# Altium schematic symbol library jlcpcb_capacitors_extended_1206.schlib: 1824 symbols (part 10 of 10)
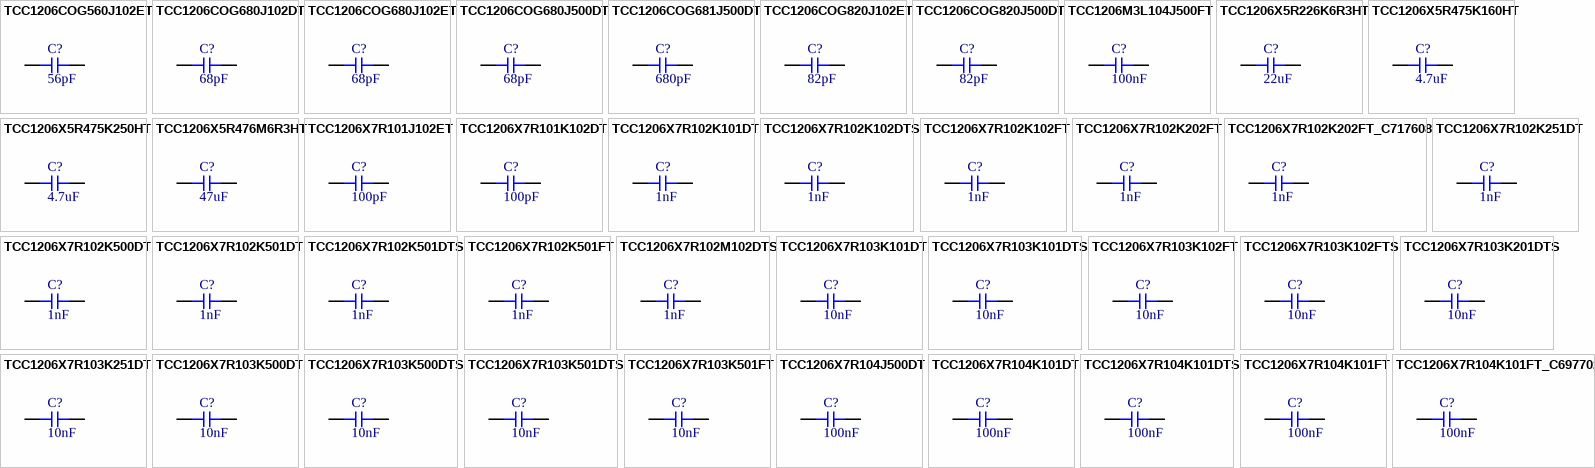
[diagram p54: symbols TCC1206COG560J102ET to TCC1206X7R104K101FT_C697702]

## TCC1206COG680J102DT
designator C?  Capacitance: 68pF  (hidden comment: *)
Capacitor, Ceramic (MLCC), 68pF, ±5%, 1kV, C0G, ±5%, SMD 1206; Manufacturer: CCTC; Manufacturer Part Number: TCC1206COG680J102DT
footprint CAP-1206 (1206 (3216M) Capacitor)
pins: 1, 2

## TCC1206COG680J102ET
designator C?  Capacitance: 68pF  (hidden comment: *)
Capacitor, Ceramic (MLCC), 68pF, ±5%, 1kV, C0G, ±5%, SMD 1206; Manufacturer: CCTC; Manufacturer Part Number: TCC1206COG680J102ET
footprint CAP-1206 (1206 (3216M) Capacitor)
pins: 1, 2

## TCC1206COG680J500DT
designator C?  Capacitance: 68pF  (hidden comment: *)
Capacitor, Ceramic (MLCC), 68pF, ±5%, 50V, C0G, ±5%, SMD 1206; Manufacturer: CCTC; Manufacturer Part Number: TCC1206COG680J500DT
footprint CAP-1206 (1206 (3216M) Capacitor)
pins: 1, 2

## TCC1206COG681J500DT
designator C?  Capacitance: 680pF  (hidden comment: *)
Capacitor, Ceramic (MLCC), 680pF, ±5%, 50V, C0G, ±5%, SMD 1206; Manufacturer: CCTC; Manufacturer Part Number: TCC1206COG681J500DT
footprint CAP-1206 (1206 (3216M) Capacitor)
pins: 1, 2

## TCC1206COG820J102ET
designator C?  Capacitance: 82pF  (hidden comment: *)
Capacitor, Ceramic (MLCC), 82pF, ±5%, 1kV, C0G, ±5%, SMD 1206; Manufacturer: CCTC; Manufacturer Part Number: TCC1206COG820J102ET
footprint CAP-1206 (1206 (3216M) Capacitor)
pins: 1, 2

## TCC1206COG820J500DT
designator C?  Capacitance: 82pF  (hidden comment: *)
Capacitor, Ceramic (MLCC), 82pF, ±5%, 50V, C0G, ±5%, SMD 1206; Manufacturer: CCTC; Manufacturer Part Number: TCC1206COG820J500DT
footprint CAP-1206 (1206 (3216M) Capacitor)
pins: 1, 2

## TCC1206M3L104J500FT
designator C?  Capacitance: 100nF  (hidden comment: *)
Capacitor, Ceramic (MLCC), 100nF, ±5%, 50V, M3L, ±5%, SMD 1206; Manufacturer: CCTC; Manufacturer Part Number: TCC1206M3L104J500FT
footprint CAP-1206 (1206 (3216M) Capacitor)
pins: 1, 2

## TCC1206X5R226K6R3HT
designator C?  Capacitance: 22uF  (hidden comment: *)
Capacitor, Ceramic (MLCC), 22uF, ±10%, 6.3V, X5R, ±10%, SMD 1206; Manufacturer: CCTC; Manufacturer Part Number: TCC1206X5R226K6R3HT
footprint CAP-1206 (1206 (3216M) Capacitor)
pins: 1, 2

## TCC1206X5R475K160HT
designator C?  Capacitance: 4.7uF  (hidden comment: *)
Capacitor, Ceramic (MLCC), 4.7uF, ±10%, 16V, X5R, ±10%, SMD 1206; Manufacturer: CCTC; Manufacturer Part Number: TCC1206X5R475K160HT
footprint CAP-1206 (1206 (3216M) Capacitor)
pins: 1, 2

## TCC1206X5R475K250HT
designator C?  Capacitance: 4.7uF  (hidden comment: *)
Capacitor, Ceramic (MLCC), 4.7uF, ±10%, 25V, X5R, ±10%, SMD 1206; Manufacturer: CCTC; Manufacturer Part Number: TCC1206X5R475K250HT
footprint CAP-1206 (1206 (3216M) Capacitor)
pins: 1, 2

## TCC1206X5R476M6R3HT
designator C?  Capacitance: 47uF  (hidden comment: *)
Capacitor, Ceramic (MLCC), 47uF, ±20%, 6.3V, X5R, ±20%, SMD 1206; Manufacturer: CCTC; Manufacturer Part Number: TCC1206X5R476M6R3HT
footprint CAP-1206 (1206 (3216M) Capacitor)
pins: 1, 2

## TCC1206X7R101J102ET
designator C?  Capacitance: 100pF  (hidden comment: *)
Capacitor, Ceramic (MLCC), 100pF, ±5%, 1kV, X7R, ±5%, SMD 1206; Manufacturer: CCTC; Manufacturer Part Number: TCC1206X7R101J102ET
footprint CAP-1206 (1206 (3216M) Capacitor)
pins: 1, 2

## TCC1206X7R101K102DT
designator C?  Capacitance: 100pF  (hidden comment: *)
Capacitor, Ceramic (MLCC), 100pF, ±10%, 1kV, X7R, ±10%, SMD 1206; Manufacturer: CCTC; Manufacturer Part Number: TCC1206X7R101K102DT
footprint CAP-1206 (1206 (3216M) Capacitor)
pins: 1, 2

## TCC1206X7R102K101DT
designator C?  Capacitance: 1nF  (hidden comment: *)
Capacitor, Ceramic (MLCC), 1nF, ±10%, 100V, X7R, ±10%, SMD 1206; Manufacturer: CCTC; Manufacturer Part Number: TCC1206X7R102K101DT
footprint CAP-1206 (1206 (3216M) Capacitor)
pins: 1, 2

## TCC1206X7R102K102DTS
designator C?  Capacitance: 1nF  (hidden comment: *)
Capacitor, Ceramic (MLCC), 1nF, ±10%, 1kV, X7R, ±10%, SMD 1206; Manufacturer: CCTC; Manufacturer Part Number: TCC1206X7R102K102DTS
footprint CAP-1206 (1206 (3216M) Capacitor)
pins: 1, 2

## TCC1206X7R102K102FT
designator C?  Capacitance: 1nF  (hidden comment: *)
Capacitor, Ceramic (MLCC), 1nF, ±10%, 1kV, X7R, ±10%, SMD 1206; Manufacturer: CCTC; Manufacturer Part Number: TCC1206X7R102K102FT
footprint CAP-1206 (1206 (3216M) Capacitor)
pins: 1, 2

## TCC1206X7R102K202FT
designator C?  Capacitance: 1nF  (hidden comment: *)
Capacitor, Ceramic (MLCC), 1nF, ±10%, 2kV, X7R, ±10%, SMD 1206; Manufacturer: CCTC; Manufacturer Part Number: TCC1206X7R102K202FT
footprint CAP-1206 (1206 (3216M) Capacitor)
pins: 1, 2

## TCC1206X7R102K202FT_C717608
designator C?  Capacitance: 1nF  (hidden comment: *)
Capacitor, Ceramic (MLCC), 1nF, ±10%, 2kV, X7R, ±10%, SMD 1206; Manufacturer: CCTC; Manufacturer Part Number: TCC1206X7R102K202FT
footprint CAP-1206 (1206 (3216M) Capacitor)
pins: 1, 2

## TCC1206X7R102K251DT
designator C?  Capacitance: 1nF  (hidden comment: *)
Capacitor, Ceramic (MLCC), 1nF, ±10%, 250V, X7R, ±10%, SMD 1206; Manufacturer: CCTC; Manufacturer Part Number: TCC1206X7R102K251DT
footprint CAP-1206 (1206 (3216M) Capacitor)
pins: 1, 2

## TCC1206X7R102K500DT
designator C?  Capacitance: 1nF  (hidden comment: *)
Capacitor, Ceramic (MLCC), 1nF, ±10%, 50V, X7R, ±10%, SMD 1206; Manufacturer: CCTC; Manufacturer Part Number: TCC1206X7R102K500DT
footprint CAP-1206 (1206 (3216M) Capacitor)
pins: 1, 2

## TCC1206X7R102K501DT
designator C?  Capacitance: 1nF  (hidden comment: *)
Capacitor, Ceramic (MLCC), 1nF, ±10%, 500V, X7R, ±10%, SMD 1206; Manufacturer: CCTC; Manufacturer Part Number: TCC1206X7R102K501DT
footprint CAP-1206 (1206 (3216M) Capacitor)
pins: 1, 2

## TCC1206X7R102K501DTS
designator C?  Capacitance: 1nF  (hidden comment: *)
Capacitor, Ceramic (MLCC), 1nF, ±10%, 500V, X7R, ±10%, SMD 1206; Manufacturer: CCTC; Manufacturer Part Number: TCC1206X7R102K501DTS
footprint CAP-1206 (1206 (3216M) Capacitor)
pins: 1, 2

## TCC1206X7R102K501FT
designator C?  Capacitance: 1nF  (hidden comment: *)
Capacitor, Ceramic (MLCC), 1nF, ±10%, 500V, X7R, ±10%, SMD 1206; Manufacturer: CCTC; Manufacturer Part Number: TCC1206X7R102K501FT
footprint CAP-1206 (1206 (3216M) Capacitor)
pins: 1, 2

## TCC1206X7R102M102DTS
designator C?  Capacitance: 1nF  (hidden comment: *)
Capacitor, Ceramic (MLCC), 1nF, ±20%, 1kV, X7R, ±20%, SMD 1206; Manufacturer: CCTC; Manufacturer Part Number: TCC1206X7R102M102DTS
footprint CAP-1206 (1206 (3216M) Capacitor)
pins: 1, 2

## TCC1206X7R103K101DT
designator C?  Capacitance: 10nF  (hidden comment: *)
Capacitor, Ceramic (MLCC), 10nF, ±10%, 100V, X7R, ±10%, SMD 1206; Manufacturer: CCTC; Manufacturer Part Number: TCC1206X7R103K101DT
footprint CAP-1206 (1206 (3216M) Capacitor)
pins: 1, 2

## TCC1206X7R103K101DTS
designator C?  Capacitance: 10nF  (hidden comment: *)
Capacitor, Ceramic (MLCC), 10nF, ±10%, 100V, X7R, ±10%, SMD 1206; Manufacturer: CCTC; Manufacturer Part Number: TCC1206X7R103K101DTS
footprint CAP-1206 (1206 (3216M) Capacitor)
pins: 1, 2

## TCC1206X7R103K102FT
designator C?  Capacitance: 10nF  (hidden comment: *)
Capacitor, Ceramic (MLCC), 10nF, ±10%, 1kV, X7R, ±10%, SMD 1206; Manufacturer: CCTC; Manufacturer Part Number: TCC1206X7R103K102FT
footprint CAP-1206 (1206 (3216M) Capacitor)
pins: 1, 2

## TCC1206X7R103K102FTS
designator C?  Capacitance: 10nF  (hidden comment: *)
Capacitor, Ceramic (MLCC), 10nF, ±10%, 1kV, X7R, ±10%, SMD 1206; Manufacturer: CCTC; Manufacturer Part Number: TCC1206X7R103K102FTS
footprint CAP-1206 (1206 (3216M) Capacitor)
pins: 1, 2

## TCC1206X7R103K201DTS
designator C?  Capacitance: 10nF  (hidden comment: *)
Capacitor, Ceramic (MLCC), 10nF, ±10%, 200V, X7R, ±10%, SMD 1206; Manufacturer: CCTC; Manufacturer Part Number: TCC1206X7R103K201DTS
footprint CAP-1206 (1206 (3216M) Capacitor)
pins: 1, 2

## TCC1206X7R103K251DT
designator C?  Capacitance: 10nF  (hidden comment: *)
Capacitor, Ceramic (MLCC), 10nF, ±10%, 250V, X7R, ±10%, SMD 1206; Manufacturer: CCTC; Manufacturer Part Number: TCC1206X7R103K251DT
footprint CAP-1206 (1206 (3216M) Capacitor)
pins: 1, 2

## TCC1206X7R103K500DT
designator C?  Capacitance: 10nF  (hidden comment: *)
Capacitor, Ceramic (MLCC), 10nF, ±10%, 50V, X7R, ±10%, SMD 1206; Manufacturer: CCTC; Manufacturer Part Number: TCC1206X7R103K500DT
footprint CAP-1206 (1206 (3216M) Capacitor)
pins: 1, 2

## TCC1206X7R103K500DTS
designator C?  Capacitance: 10nF  (hidden comment: *)
Capacitor, Ceramic (MLCC), 10nF, ±10%, 50V, X7R, ±10%, SMD 1206; Manufacturer: CCTC; Manufacturer Part Number: TCC1206X7R103K500DTS
footprint CAP-1206 (1206 (3216M) Capacitor)
pins: 1, 2

## TCC1206X7R103K501DTS
designator C?  Capacitance: 10nF  (hidden comment: *)
Capacitor, Ceramic (MLCC), 10nF, ±10%, 500V, X7R, ±10%, SMD 1206; Manufacturer: CCTC; Manufacturer Part Number: TCC1206X7R103K501DTS
footprint CAP-1206 (1206 (3216M) Capacitor)
pins: 1, 2

## TCC1206X7R103K501FT
designator C?  Capacitance: 10nF  (hidden comment: *)
Capacitor, Ceramic (MLCC), 10nF, ±10%, 500V, X7R, ±10%, SMD 1206; Manufacturer: CCTC; Manufacturer Part Number: TCC1206X7R103K501FT
footprint CAP-1206 (1206 (3216M) Capacitor)
pins: 1, 2

## TCC1206X7R104J500DT
designator C?  Capacitance: 100nF  (hidden comment: *)
Capacitor, Ceramic (MLCC), 100nF, ±5%, 50V, X7R, ±5%, SMD 1206; Manufacturer: CCTC; Manufacturer Part Number: TCC1206X7R104J500DT
footprint CAP-1206 (1206 (3216M) Capacitor)
pins: 1, 2

## TCC1206X7R104K101DT
designator C?  Capacitance: 100nF  (hidden comment: *)
Capacitor, Ceramic (MLCC), 100nF, ±10%, 100V, X7R, ±10%, SMD 1206; Manufacturer: CCTC; Manufacturer Part Number: TCC1206X7R104K101DT
footprint CAP-1206 (1206 (3216M) Capacitor)
pins: 1, 2

## TCC1206X7R104K101DTS
designator C?  Capacitance: 100nF  (hidden comment: *)
Capacitor, Ceramic (MLCC), 100nF, ±10%, 100V, X7R, ±10%, SMD 1206; Manufacturer: CCTC; Manufacturer Part Number: TCC1206X7R104K101DTS
footprint CAP-1206 (1206 (3216M) Capacitor)
pins: 1, 2

## TCC1206X7R104K101FT
designator C?  Capacitance: 100nF  (hidden comment: *)
Capacitor, Ceramic (MLCC), 100nF, ±10%, 100V, X7R, ±10%, SMD 1206; Manufacturer: CCTC; Manufacturer Part Number: TCC1206X7R104K101FT
footprint CAP-1206 (1206 (3216M) Capacitor)
pins: 1, 2

## TCC1206X7R104K101FT_C697702
designator C?  Capacitance: 100nF  (hidden comment: *)
Capacitor, Ceramic (MLCC), 100nF, ±10%, 100V, X7R, ±10%, SMD 1206; Manufacturer: CCTC; Manufacturer Part Number: TCC1206X7R104K101FT
footprint CAP-1206 (1206 (3216M) Capacitor)
pins: 1, 2

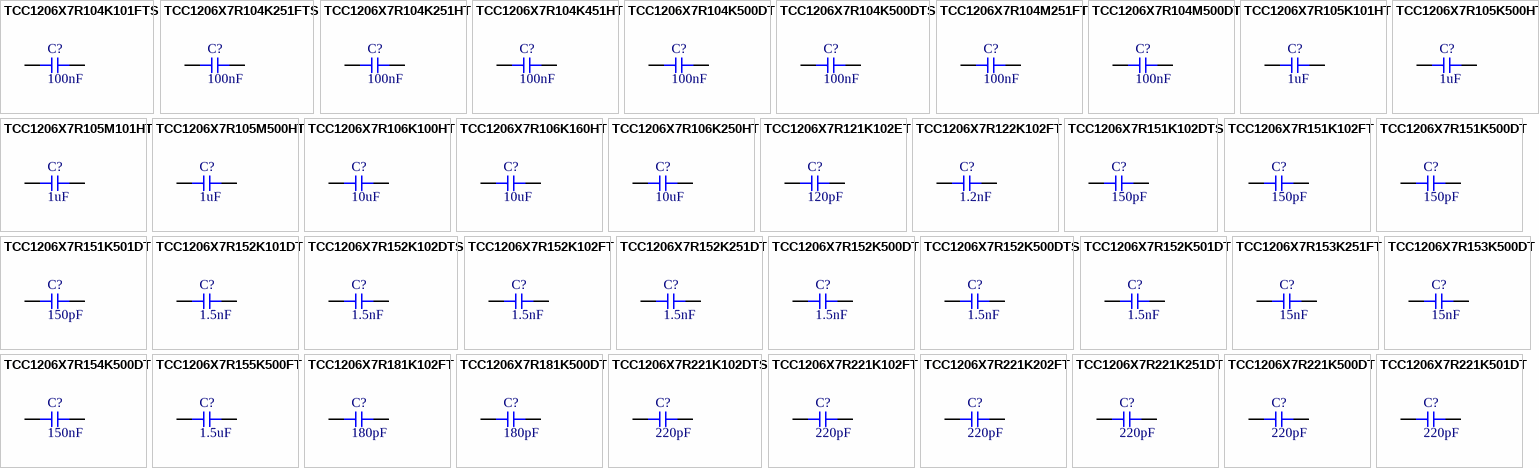
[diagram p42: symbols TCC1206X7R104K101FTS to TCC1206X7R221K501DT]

## TCC1206X7R104K101FTS
designator C?  Capacitance: 100nF  (hidden comment: *)
Capacitor, Ceramic (MLCC), 100nF, ±10%, 100V, X7R, ±10%, SMD 1206; Manufacturer: CCTC; Manufacturer Part Number: TCC1206X7R104K101FTS
footprint CAP-1206 (1206 (3216M) Capacitor)
pins: 1, 2

## TCC1206X7R104K251FTS
designator C?  Capacitance: 100nF  (hidden comment: *)
Capacitor, Ceramic (MLCC), 100nF, ±10%, 250V, X7R, ±10%, SMD 1206; Manufacturer: CCTC; Manufacturer Part Number: TCC1206X7R104K251FTS
footprint CAP-1206 (1206 (3216M) Capacitor)
pins: 1, 2

## TCC1206X7R104K251HT
designator C?  Capacitance: 100nF  (hidden comment: *)
Capacitor, Ceramic (MLCC), 100nF, ±10%, 250V, X7R, ±10%, SMD 1206; Manufacturer: CCTC; Manufacturer Part Number: TCC1206X7R104K251HT
footprint CAP-1206 (1206 (3216M) Capacitor)
pins: 1, 2

## TCC1206X7R104K451HT
designator C?  Capacitance: 100nF  (hidden comment: *)
Capacitor, Ceramic (MLCC), 100nF, ±10%, 450V, X7R, ±10%, SMD 1206; Manufacturer: CCTC; Manufacturer Part Number: TCC1206X7R104K451HT
footprint CAP-1206 (1206 (3216M) Capacitor)
pins: 1, 2

## TCC1206X7R104K500DT
designator C?  Capacitance: 100nF  (hidden comment: *)
Capacitor, Ceramic (MLCC), 100nF, ±10%, 50V, X7R, ±10%, SMD 1206; Manufacturer: CCTC; Manufacturer Part Number: TCC1206X7R104K500DT
footprint CAP-1206 (1206 (3216M) Capacitor)
pins: 1, 2

## TCC1206X7R104K500DTS
designator C?  Capacitance: 100nF  (hidden comment: *)
Capacitor, Ceramic (MLCC), 100nF, ±10%, 50V, X7R, ±10%, SMD 1206; Manufacturer: CCTC; Manufacturer Part Number: TCC1206X7R104K500DTS
footprint CAP-1206 (1206 (3216M) Capacitor)
pins: 1, 2

## TCC1206X7R104M251FT
designator C?  Capacitance: 100nF  (hidden comment: *)
Capacitor, Ceramic (MLCC), 100nF, ±20%, 250V, X7R, ±20%, SMD 1206; Manufacturer: CCTC; Manufacturer Part Number: TCC1206X7R104M251FT
footprint CAP-1206 (1206 (3216M) Capacitor)
pins: 1, 2

## TCC1206X7R104M500DT
designator C?  Capacitance: 100nF  (hidden comment: *)
Capacitor, Ceramic (MLCC), 100nF, ±20%, 50V, X7R, ±20%, SMD 1206; Manufacturer: CCTC; Manufacturer Part Number: TCC1206X7R104M500DT
footprint CAP-1206 (1206 (3216M) Capacitor)
pins: 1, 2

## TCC1206X7R105K101HT
designator C?  Capacitance: 1uF  (hidden comment: *)
Capacitor, Ceramic (MLCC), 1uF, ±10%, 100V, X7R, ±10%, SMD 1206; Manufacturer: CCTC; Manufacturer Part Number: TCC1206X7R105K101HT
footprint CAP-1206 (1206 (3216M) Capacitor)
pins: 1, 2

## TCC1206X7R105K500HT
designator C?  Capacitance: 1uF  (hidden comment: *)
Capacitor, Ceramic (MLCC), 1uF, ±10%, 50V, X7R, ±10%, SMD 1206; Manufacturer: CCTC; Manufacturer Part Number: TCC1206X7R105K500HT
footprint CAP-1206 (1206 (3216M) Capacitor)
pins: 1, 2

## TCC1206X7R105M101HT
designator C?  Capacitance: 1uF  (hidden comment: *)
Capacitor, Ceramic (MLCC), 1uF, ±20%, 100V, X7R, ±20%, SMD 1206; Manufacturer: CCTC; Manufacturer Part Number: TCC1206X7R105M101HT
footprint CAP-1206 (1206 (3216M) Capacitor)
pins: 1, 2

## TCC1206X7R105M500HT
designator C?  Capacitance: 1uF  (hidden comment: *)
Capacitor, Ceramic (MLCC), 1uF, ±20%, 50V, X7R, ±20%, SMD 1206; Manufacturer: CCTC; Manufacturer Part Number: TCC1206X7R105M500HT
footprint CAP-1206 (1206 (3216M) Capacitor)
pins: 1, 2

## TCC1206X7R106K100HT
designator C?  Capacitance: 10uF  (hidden comment: *)
Capacitor, Ceramic (MLCC), 10uF, ±10%, 10V, X7R, ±10%, SMD 1206; Manufacturer: CCTC; Manufacturer Part Number: TCC1206X7R106K100HT
footprint CAP-1206 (1206 (3216M) Capacitor)
pins: 1, 2

## TCC1206X7R106K160HT
designator C?  Capacitance: 10uF  (hidden comment: *)
Capacitor, Ceramic (MLCC), 10uF, ±10%, 16V, X7R, ±10%, SMD 1206; Manufacturer: CCTC; Manufacturer Part Number: TCC1206X7R106K160HT
footprint CAP-1206 (1206 (3216M) Capacitor)
pins: 1, 2

## TCC1206X7R106K250HT
designator C?  Capacitance: 10uF  (hidden comment: *)
Capacitor, Ceramic (MLCC), 10uF, ±10%, 25V, X7R, ±10%, SMD 1206; Manufacturer: CCTC; Manufacturer Part Number: TCC1206X7R106K250HT
footprint CAP-1206 (1206 (3216M) Capacitor)
pins: 1, 2

## TCC1206X7R121K102ET
designator C?  Capacitance: 120pF  (hidden comment: *)
Capacitor, Ceramic (MLCC), 120pF, ±10%, 1kV, X7R, ±10%, SMD 1206; Manufacturer: CCTC; Manufacturer Part Number: TCC1206X7R121K102ET
footprint CAP-1206 (1206 (3216M) Capacitor)
pins: 1, 2

## TCC1206X7R122K102FT
designator C?  Capacitance: 1.2nF  (hidden comment: *)
Capacitor, Ceramic (MLCC), 1.2nF, ±10%, 1kV, X7R, ±10%, SMD 1206; Manufacturer: CCTC; Manufacturer Part Number: TCC1206X7R122K102FT
footprint CAP-1206 (1206 (3216M) Capacitor)
pins: 1, 2

## TCC1206X7R151K102DTS
designator C?  Capacitance: 150pF  (hidden comment: *)
Capacitor, Ceramic (MLCC), 150pF, ±10%, 1kV, X7R, ±10%, SMD 1206; Manufacturer: CCTC; Manufacturer Part Number: TCC1206X7R151K102DTS
footprint CAP-1206 (1206 (3216M) Capacitor)
pins: 1, 2

## TCC1206X7R151K102FT
designator C?  Capacitance: 150pF  (hidden comment: *)
Capacitor, Ceramic (MLCC), 150pF, ±10%, 1kV, X7R, ±10%, SMD 1206; Manufacturer: CCTC; Manufacturer Part Number: TCC1206X7R151K102FT
footprint CAP-1206 (1206 (3216M) Capacitor)
pins: 1, 2

## TCC1206X7R151K500DT
designator C?  Capacitance: 150pF  (hidden comment: *)
Capacitor, Ceramic (MLCC), 150pF, ±10%, 50V, X7R, ±10%, SMD 1206; Manufacturer: CCTC; Manufacturer Part Number: TCC1206X7R151K500DT
footprint CAP-1206 (1206 (3216M) Capacitor)
pins: 1, 2

## TCC1206X7R151K501DT
designator C?  Capacitance: 150pF  (hidden comment: *)
Capacitor, Ceramic (MLCC), 150pF, ±10%, 500V, X7R, ±10%, SMD 1206; Manufacturer: CCTC; Manufacturer Part Number: TCC1206X7R151K501DT
footprint CAP-1206 (1206 (3216M) Capacitor)
pins: 1, 2

## TCC1206X7R152K101DT
designator C?  Capacitance: 1.5nF  (hidden comment: *)
Capacitor, Ceramic (MLCC), 1.5nF, ±10%, 100V, X7R, ±10%, SMD 1206; Manufacturer: CCTC; Manufacturer Part Number: TCC1206X7R152K101DT
footprint CAP-1206 (1206 (3216M) Capacitor)
pins: 1, 2

## TCC1206X7R152K102DTS
designator C?  Capacitance: 1.5nF  (hidden comment: *)
Capacitor, Ceramic (MLCC), 1.5nF, ±10%, 1kV, X7R, ±10%, SMD 1206; Manufacturer: CCTC; Manufacturer Part Number: TCC1206X7R152K102DTS
footprint CAP-1206 (1206 (3216M) Capacitor)
pins: 1, 2

## TCC1206X7R152K102FT
designator C?  Capacitance: 1.5nF  (hidden comment: *)
Capacitor, Ceramic (MLCC), 1.5nF, ±10%, 1kV, X7R, ±10%, SMD 1206; Manufacturer: CCTC; Manufacturer Part Number: TCC1206X7R152K102FT
footprint CAP-1206 (1206 (3216M) Capacitor)
pins: 1, 2

## TCC1206X7R152K251DT
designator C?  Capacitance: 1.5nF  (hidden comment: *)
Capacitor, Ceramic (MLCC), 1.5nF, ±10%, 250V, X7R, ±10%, SMD 1206; Manufacturer: CCTC; Manufacturer Part Number: TCC1206X7R152K251DT
footprint CAP-1206 (1206 (3216M) Capacitor)
pins: 1, 2

## TCC1206X7R152K500DT
designator C?  Capacitance: 1.5nF  (hidden comment: *)
Capacitor, Ceramic (MLCC), 1.5nF, ±10%, 50V, X7R, ±10%, SMD 1206; Manufacturer: CCTC; Manufacturer Part Number: TCC1206X7R152K500DT
footprint CAP-1206 (1206 (3216M) Capacitor)
pins: 1, 2

## TCC1206X7R152K500DTS
designator C?  Capacitance: 1.5nF  (hidden comment: *)
Capacitor, Ceramic (MLCC), 1.5nF, ±10%, 50V, X7R, ±10%, SMD 1206; Manufacturer: CCTC; Manufacturer Part Number: TCC1206X7R152K500DTS
footprint CAP-1206 (1206 (3216M) Capacitor)
pins: 1, 2

## TCC1206X7R152K501DT
designator C?  Capacitance: 1.5nF  (hidden comment: *)
Capacitor, Ceramic (MLCC), 1.5nF, ±10%, 500V, X7R, ±10%, SMD 1206; Manufacturer: CCTC; Manufacturer Part Number: TCC1206X7R152K501DT
footprint CAP-1206 (1206 (3216M) Capacitor)
pins: 1, 2

## TCC1206X7R153K251FT
designator C?  Capacitance: 15nF  (hidden comment: *)
Capacitor, Ceramic (MLCC), 15nF, ±10%, 250V, X7R, ±10%, SMD 1206; Manufacturer: CCTC; Manufacturer Part Number: TCC1206X7R153K251FT
footprint CAP-1206 (1206 (3216M) Capacitor)
pins: 1, 2

## TCC1206X7R153K500DT
designator C?  Capacitance: 15nF  (hidden comment: *)
Capacitor, Ceramic (MLCC), 15nF, ±10%, 50V, X7R, ±10%, SMD 1206; Manufacturer: CCTC; Manufacturer Part Number: TCC1206X7R153K500DT
footprint CAP-1206 (1206 (3216M) Capacitor)
pins: 1, 2

## TCC1206X7R154K500DT
designator C?  Capacitance: 150nF  (hidden comment: *)
Capacitor, Ceramic (MLCC), 150nF, ±10%, 50V, X7R, ±10%, SMD 1206; Manufacturer: CCTC; Manufacturer Part Number: TCC1206X7R154K500DT
footprint CAP-1206 (1206 (3216M) Capacitor)
pins: 1, 2

## TCC1206X7R155K500FT
designator C?  Capacitance: 1.5uF  (hidden comment: *)
Capacitor, Ceramic (MLCC), 1.5uF, ±10%, 50V, X7R, ±10%, SMD 1206; Manufacturer: CCTC; Manufacturer Part Number: TCC1206X7R155K500FT
footprint CAP-1206 (1206 (3216M) Capacitor)
pins: 1, 2

## TCC1206X7R181K102FT
designator C?  Capacitance: 180pF  (hidden comment: *)
Capacitor, Ceramic (MLCC), 180pF, ±10%, 1kV, X7R, ±10%, SMD 1206; Manufacturer: CCTC; Manufacturer Part Number: TCC1206X7R181K102FT
footprint CAP-1206 (1206 (3216M) Capacitor)
pins: 1, 2

## TCC1206X7R181K500DT
designator C?  Capacitance: 180pF  (hidden comment: *)
Capacitor, Ceramic (MLCC), 180pF, ±10%, 50V, X7R, ±10%, SMD 1206; Manufacturer: CCTC; Manufacturer Part Number: TCC1206X7R181K500DT
footprint CAP-1206 (1206 (3216M) Capacitor)
pins: 1, 2

## TCC1206X7R221K102DTS
designator C?  Capacitance: 220pF  (hidden comment: *)
Capacitor, Ceramic (MLCC), 220pF, ±10%, 1kV, X7R, ±10%, SMD 1206; Manufacturer: CCTC; Manufacturer Part Number: TCC1206X7R221K102DTS
footprint CAP-1206 (1206 (3216M) Capacitor)
pins: 1, 2

## TCC1206X7R221K102FT
designator C?  Capacitance: 220pF  (hidden comment: *)
Capacitor, Ceramic (MLCC), 220pF, ±10%, 1kV, X7R, ±10%, SMD 1206; Manufacturer: CCTC; Manufacturer Part Number: TCC1206X7R221K102FT
footprint CAP-1206 (1206 (3216M) Capacitor)
pins: 1, 2

## TCC1206X7R221K202FT
designator C?  Capacitance: 220pF  (hidden comment: *)
Capacitor, Ceramic (MLCC), 220pF, ±10%, 2kV, X7R, ±10%, SMD 1206; Manufacturer: CCTC; Manufacturer Part Number: TCC1206X7R221K202FT
footprint CAP-1206 (1206 (3216M) Capacitor)
pins: 1, 2

## TCC1206X7R221K251DT
designator C?  Capacitance: 220pF  (hidden comment: *)
Capacitor, Ceramic (MLCC), 220pF, ±10%, 250V, X7R, ±10%, SMD 1206; Manufacturer: CCTC; Manufacturer Part Number: TCC1206X7R221K251DT
footprint CAP-1206 (1206 (3216M) Capacitor)
pins: 1, 2

## TCC1206X7R221K500DT
designator C?  Capacitance: 220pF  (hidden comment: *)
Capacitor, Ceramic (MLCC), 220pF, ±10%, 50V, X7R, ±10%, SMD 1206; Manufacturer: CCTC; Manufacturer Part Number: TCC1206X7R221K500DT
footprint CAP-1206 (1206 (3216M) Capacitor)
pins: 1, 2

## TCC1206X7R221K501DT
designator C?  Capacitance: 220pF  (hidden comment: *)
Capacitor, Ceramic (MLCC), 220pF, ±10%, 500V, X7R, ±10%, SMD 1206; Manufacturer: CCTC; Manufacturer Part Number: TCC1206X7R221K501DT
footprint CAP-1206 (1206 (3216M) Capacitor)
pins: 1, 2

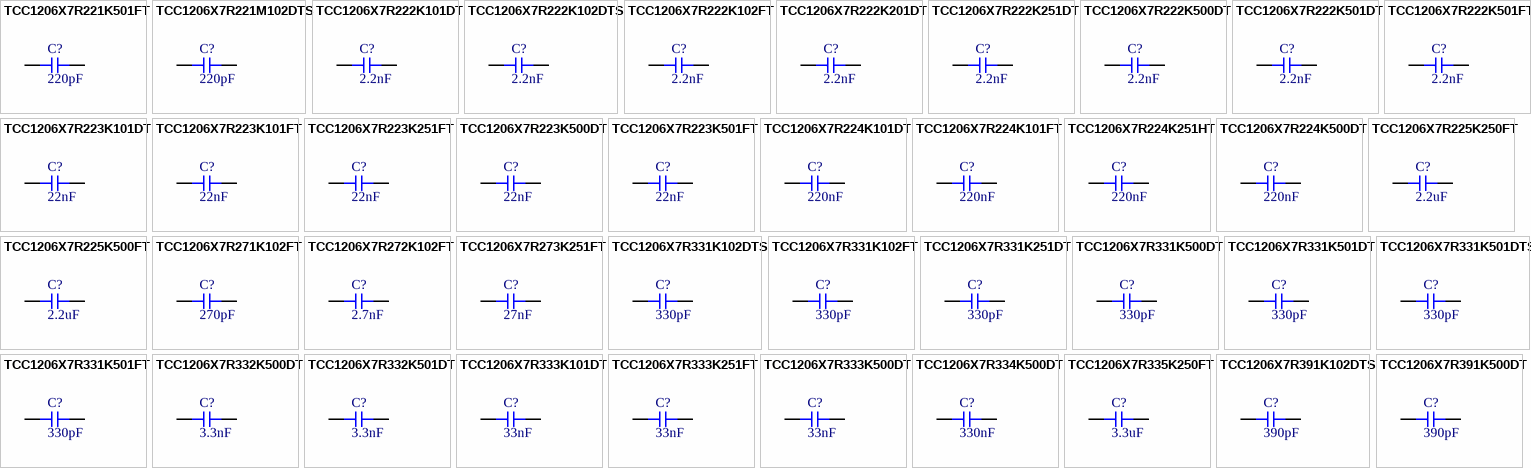
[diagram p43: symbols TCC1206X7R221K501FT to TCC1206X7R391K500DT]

## TCC1206X7R221K501FT
designator C?  Capacitance: 220pF  (hidden comment: *)
Capacitor, Ceramic (MLCC), 220pF, ±10%, 500V, X7R, ±10%, SMD 1206; Manufacturer: CCTC; Manufacturer Part Number: TCC1206X7R221K501FT
footprint CAP-1206 (1206 (3216M) Capacitor)
pins: 1, 2

## TCC1206X7R221M102DTS
designator C?  Capacitance: 220pF  (hidden comment: *)
Capacitor, Ceramic (MLCC), 220pF, ±20%, 1kV, X7R, ±20%, SMD 1206; Manufacturer: CCTC; Manufacturer Part Number: TCC1206X7R221M102DTS
footprint CAP-1206 (1206 (3216M) Capacitor)
pins: 1, 2

## TCC1206X7R222K101DT
designator C?  Capacitance: 2.2nF  (hidden comment: *)
Capacitor, Ceramic (MLCC), 2.2nF, ±10%, 100V, X7R, ±10%, SMD 1206; Manufacturer: CCTC; Manufacturer Part Number: TCC1206X7R222K101DT
footprint CAP-1206 (1206 (3216M) Capacitor)
pins: 1, 2

## TCC1206X7R222K102DTS
designator C?  Capacitance: 2.2nF  (hidden comment: *)
Capacitor, Ceramic (MLCC), 2.2nF, ±10%, 1kV, X7R, ±10%, SMD 1206; Manufacturer: CCTC; Manufacturer Part Number: TCC1206X7R222K102DTS
footprint CAP-1206 (1206 (3216M) Capacitor)
pins: 1, 2

## TCC1206X7R222K102FT
designator C?  Capacitance: 2.2nF  (hidden comment: *)
Capacitor, Ceramic (MLCC), 2.2nF, ±10%, 1kV, X7R, ±10%, SMD 1206; Manufacturer: CCTC; Manufacturer Part Number: TCC1206X7R222K102FT
footprint CAP-1206 (1206 (3216M) Capacitor)
pins: 1, 2

## TCC1206X7R222K201DT
designator C?  Capacitance: 2.2nF  (hidden comment: *)
Capacitor, Ceramic (MLCC), 2.2nF, ±10%, 200V, X7R, ±10%, SMD 1206; Manufacturer: CCTC; Manufacturer Part Number: TCC1206X7R222K201DT
footprint CAP-1206 (1206 (3216M) Capacitor)
pins: 1, 2

## TCC1206X7R222K251DT
designator C?  Capacitance: 2.2nF  (hidden comment: *)
Capacitor, Ceramic (MLCC), 2.2nF, ±10%, 250V, X7R, ±10%, SMD 1206; Manufacturer: CCTC; Manufacturer Part Number: TCC1206X7R222K251DT
footprint CAP-1206 (1206 (3216M) Capacitor)
pins: 1, 2

## TCC1206X7R222K500DT
designator C?  Capacitance: 2.2nF  (hidden comment: *)
Capacitor, Ceramic (MLCC), 2.2nF, ±10%, 50V, X7R, ±10%, SMD 1206; Manufacturer: CCTC; Manufacturer Part Number: TCC1206X7R222K500DT
footprint CAP-1206 (1206 (3216M) Capacitor)
pins: 1, 2

## TCC1206X7R222K501DT
designator C?  Capacitance: 2.2nF  (hidden comment: *)
Capacitor, Ceramic (MLCC), 2.2nF, ±10%, 500V, X7R, ±10%, SMD 1206; Manufacturer: CCTC; Manufacturer Part Number: TCC1206X7R222K501DT
footprint CAP-1206 (1206 (3216M) Capacitor)
pins: 1, 2

## TCC1206X7R222K501FT
designator C?  Capacitance: 2.2nF  (hidden comment: *)
Capacitor, Ceramic (MLCC), 2.2nF, ±10%, 500V, X7R, ±10%, SMD 1206; Manufacturer: CCTC; Manufacturer Part Number: TCC1206X7R222K501FT
footprint CAP-1206 (1206 (3216M) Capacitor)
pins: 1, 2

## TCC1206X7R223K101DT
designator C?  Capacitance: 22nF  (hidden comment: *)
Capacitor, Ceramic (MLCC), 22nF, ±10%, 100V, X7R, ±10%, SMD 1206; Manufacturer: CCTC; Manufacturer Part Number: TCC1206X7R223K101DT
footprint CAP-1206 (1206 (3216M) Capacitor)
pins: 1, 2

## TCC1206X7R223K101FT
designator C?  Capacitance: 22nF  (hidden comment: *)
Capacitor, Ceramic (MLCC), 22nF, ±10%, 100V, X7R, ±10%, SMD 1206; Manufacturer: CCTC; Manufacturer Part Number: TCC1206X7R223K101FT
footprint CAP-1206 (1206 (3216M) Capacitor)
pins: 1, 2

## TCC1206X7R223K251FT
designator C?  Capacitance: 22nF  (hidden comment: *)
Capacitor, Ceramic (MLCC), 22nF, ±10%, 250V, X7R, ±10%, SMD 1206; Manufacturer: CCTC; Manufacturer Part Number: TCC1206X7R223K251FT
footprint CAP-1206 (1206 (3216M) Capacitor)
pins: 1, 2

## TCC1206X7R223K500DT
designator C?  Capacitance: 22nF  (hidden comment: *)
Capacitor, Ceramic (MLCC), 22nF, ±10%, 50V, X7R, ±10%, SMD 1206; Manufacturer: CCTC; Manufacturer Part Number: TCC1206X7R223K500DT
footprint CAP-1206 (1206 (3216M) Capacitor)
pins: 1, 2

## TCC1206X7R223K501FT
designator C?  Capacitance: 22nF  (hidden comment: *)
Capacitor, Ceramic (MLCC), 22nF, ±10%, 500V, X7R, ±10%, SMD 1206; Manufacturer: CCTC; Manufacturer Part Number: TCC1206X7R223K501FT
footprint CAP-1206 (1206 (3216M) Capacitor)
pins: 1, 2

## TCC1206X7R224K101DT
designator C?  Capacitance: 220nF  (hidden comment: *)
Capacitor, Ceramic (MLCC), 220nF, ±10%, 100V, X7R, ±10%, SMD 1206; Manufacturer: CCTC; Manufacturer Part Number: TCC1206X7R224K101DT
footprint CAP-1206 (1206 (3216M) Capacitor)
pins: 1, 2

## TCC1206X7R224K101FT
designator C?  Capacitance: 220nF  (hidden comment: *)
Capacitor, Ceramic (MLCC), 220nF, ±10%, 100V, X7R, ±10%, SMD 1206; Manufacturer: CCTC; Manufacturer Part Number: TCC1206X7R224K101FT
footprint CAP-1206 (1206 (3216M) Capacitor)
pins: 1, 2

## TCC1206X7R224K251HT
designator C?  Capacitance: 220nF  (hidden comment: *)
Capacitor, Ceramic (MLCC), 220nF, ±10%, 250V, X7R, ±10%, SMD 1206; Manufacturer: CCTC; Manufacturer Part Number: TCC1206X7R224K251HT
footprint CAP-1206 (1206 (3216M) Capacitor)
pins: 1, 2

## TCC1206X7R224K500DT
designator C?  Capacitance: 220nF  (hidden comment: *)
Capacitor, Ceramic (MLCC), 220nF, ±10%, 50V, X7R, ±10%, SMD 1206; Manufacturer: CCTC; Manufacturer Part Number: TCC1206X7R224K500DT
footprint CAP-1206 (1206 (3216M) Capacitor)
pins: 1, 2

## TCC1206X7R225K250FT
designator C?  Capacitance: 2.2uF  (hidden comment: *)
Capacitor, Ceramic (MLCC), 2.2uF, ±10%, 25V, X7R, ±10%, SMD 1206; Manufacturer: CCTC; Manufacturer Part Number: TCC1206X7R225K250FT
footprint CAP-1206 (1206 (3216M) Capacitor)
pins: 1, 2

## TCC1206X7R225K500FT
designator C?  Capacitance: 2.2uF  (hidden comment: *)
Capacitor, Ceramic (MLCC), 2.2uF, ±10%, 50V, X7R, ±10%, SMD 1206; Manufacturer: CCTC; Manufacturer Part Number: TCC1206X7R225K500FT
footprint CAP-1206 (1206 (3216M) Capacitor)
pins: 1, 2

## TCC1206X7R271K102FT
designator C?  Capacitance: 270pF  (hidden comment: *)
Capacitor, Ceramic (MLCC), 270pF, ±10%, 1kV, X7R, ±10%, SMD 1206; Manufacturer: CCTC; Manufacturer Part Number: TCC1206X7R271K102FT
footprint CAP-1206 (1206 (3216M) Capacitor)
pins: 1, 2

## TCC1206X7R272K102FT
designator C?  Capacitance: 2.7nF  (hidden comment: *)
Capacitor, Ceramic (MLCC), 2.7nF, ±10%, 1kV, X7R, ±10%, SMD 1206; Manufacturer: CCTC; Manufacturer Part Number: TCC1206X7R272K102FT
footprint CAP-1206 (1206 (3216M) Capacitor)
pins: 1, 2

## TCC1206X7R273K251FT
designator C?  Capacitance: 27nF  (hidden comment: *)
Capacitor, Ceramic (MLCC), 27nF, ±10%, 250V, X7R, ±10%, SMD 1206; Manufacturer: CCTC; Manufacturer Part Number: TCC1206X7R273K251FT
footprint CAP-1206 (1206 (3216M) Capacitor)
pins: 1, 2

## TCC1206X7R331K102DTS
designator C?  Capacitance: 330pF  (hidden comment: *)
Capacitor, Ceramic (MLCC), 330pF, ±10%, 1kV, X7R, ±10%, SMD 1206; Manufacturer: CCTC; Manufacturer Part Number: TCC1206X7R331K102DTS
footprint CAP-1206 (1206 (3216M) Capacitor)
pins: 1, 2

## TCC1206X7R331K102FT
designator C?  Capacitance: 330pF  (hidden comment: *)
Capacitor, Ceramic (MLCC), 330pF, ±10%, 1kV, X7R, ±10%, SMD 1206; Manufacturer: CCTC; Manufacturer Part Number: TCC1206X7R331K102FT
footprint CAP-1206 (1206 (3216M) Capacitor)
pins: 1, 2

## TCC1206X7R331K251DT
designator C?  Capacitance: 330pF  (hidden comment: *)
Capacitor, Ceramic (MLCC), 330pF, ±10%, 250V, X7R, ±10%, SMD 1206; Manufacturer: CCTC; Manufacturer Part Number: TCC1206X7R331K251DT
footprint CAP-1206 (1206 (3216M) Capacitor)
pins: 1, 2

## TCC1206X7R331K500DT
designator C?  Capacitance: 330pF  (hidden comment: *)
Capacitor, Ceramic (MLCC), 330pF, ±10%, 50V, X7R, ±10%, SMD 1206; Manufacturer: CCTC; Manufacturer Part Number: TCC1206X7R331K500DT
footprint CAP-1206 (1206 (3216M) Capacitor)
pins: 1, 2

## TCC1206X7R331K501DT
designator C?  Capacitance: 330pF  (hidden comment: *)
Capacitor, Ceramic (MLCC), 330pF, ±10%, 500V, X7R, ±10%, SMD 1206; Manufacturer: CCTC; Manufacturer Part Number: TCC1206X7R331K501DT
footprint CAP-1206 (1206 (3216M) Capacitor)
pins: 1, 2

## TCC1206X7R331K501DTS
designator C?  Capacitance: 330pF  (hidden comment: *)
Capacitor, Ceramic (MLCC), 330pF, ±10%, 500V, X7R, ±10%, SMD 1206; Manufacturer: CCTC; Manufacturer Part Number: TCC1206X7R331K501DTS
footprint CAP-1206 (1206 (3216M) Capacitor)
pins: 1, 2

## TCC1206X7R331K501FT
designator C?  Capacitance: 330pF  (hidden comment: *)
Capacitor, Ceramic (MLCC), 330pF, ±10%, 500V, X7R, ±10%, SMD 1206; Manufacturer: CCTC; Manufacturer Part Number: TCC1206X7R331K501FT
footprint CAP-1206 (1206 (3216M) Capacitor)
pins: 1, 2

## TCC1206X7R332K500DT
designator C?  Capacitance: 3.3nF  (hidden comment: *)
Capacitor, Ceramic (MLCC), 3.3nF, ±10%, 50V, X7R, ±10%, SMD 1206; Manufacturer: CCTC; Manufacturer Part Number: TCC1206X7R332K500DT
footprint CAP-1206 (1206 (3216M) Capacitor)
pins: 1, 2

## TCC1206X7R332K501DT
designator C?  Capacitance: 3.3nF  (hidden comment: *)
Capacitor, Ceramic (MLCC), 3.3nF, ±10%, 500V, X7R, ±10%, SMD 1206; Manufacturer: CCTC; Manufacturer Part Number: TCC1206X7R332K501DT
footprint CAP-1206 (1206 (3216M) Capacitor)
pins: 1, 2

## TCC1206X7R333K101DT
designator C?  Capacitance: 33nF  (hidden comment: *)
Capacitor, Ceramic (MLCC), 33nF, ±10%, 100V, X7R, ±10%, SMD 1206; Manufacturer: CCTC; Manufacturer Part Number: TCC1206X7R333K101DT
footprint CAP-1206 (1206 (3216M) Capacitor)
pins: 1, 2

## TCC1206X7R333K251FT
designator C?  Capacitance: 33nF  (hidden comment: *)
Capacitor, Ceramic (MLCC), 33nF, ±10%, 250V, X7R, ±10%, SMD 1206; Manufacturer: CCTC; Manufacturer Part Number: TCC1206X7R333K251FT
footprint CAP-1206 (1206 (3216M) Capacitor)
pins: 1, 2

## TCC1206X7R333K500DT
designator C?  Capacitance: 33nF  (hidden comment: *)
Capacitor, Ceramic (MLCC), 33nF, ±10%, 50V, X7R, ±10%, SMD 1206; Manufacturer: CCTC; Manufacturer Part Number: TCC1206X7R333K500DT
footprint CAP-1206 (1206 (3216M) Capacitor)
pins: 1, 2

## TCC1206X7R334K500DT
designator C?  Capacitance: 330nF  (hidden comment: *)
Capacitor, Ceramic (MLCC), 330nF, ±10%, 50V, X7R, ±10%, SMD 1206; Manufacturer: CCTC; Manufacturer Part Number: TCC1206X7R334K500DT
footprint CAP-1206 (1206 (3216M) Capacitor)
pins: 1, 2

## TCC1206X7R335K250FT
designator C?  Capacitance: 3.3uF  (hidden comment: *)
Capacitor, Ceramic (MLCC), 3.3uF, ±10%, 25V, X7R, ±10%, SMD 1206; Manufacturer: CCTC; Manufacturer Part Number: TCC1206X7R335K250FT
footprint CAP-1206 (1206 (3216M) Capacitor)
pins: 1, 2

## TCC1206X7R391K102DTS
designator C?  Capacitance: 390pF  (hidden comment: *)
Capacitor, Ceramic (MLCC), 390pF, ±10%, 1kV, X7R, ±10%, SMD 1206; Manufacturer: CCTC; Manufacturer Part Number: TCC1206X7R391K102DTS
footprint CAP-1206 (1206 (3216M) Capacitor)
pins: 1, 2

## TCC1206X7R391K500DT
designator C?  Capacitance: 390pF  (hidden comment: *)
Capacitor, Ceramic (MLCC), 390pF, ±10%, 50V, X7R, ±10%, SMD 1206; Manufacturer: CCTC; Manufacturer Part Number: TCC1206X7R391K500DT
footprint CAP-1206 (1206 (3216M) Capacitor)
pins: 1, 2

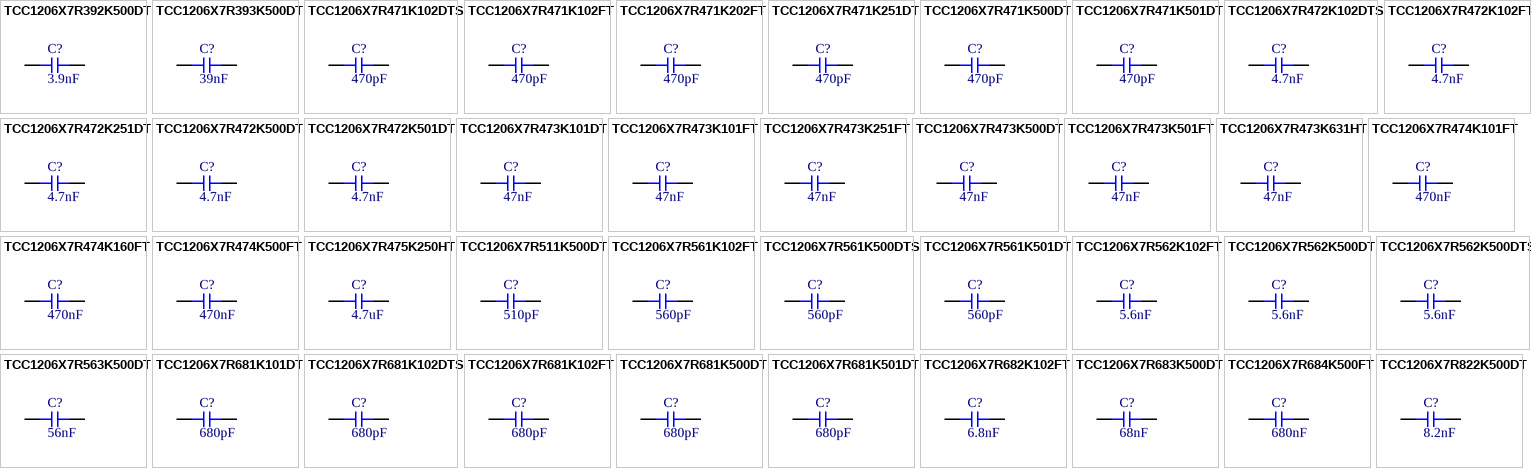
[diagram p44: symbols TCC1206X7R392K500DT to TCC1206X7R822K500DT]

## TCC1206X7R392K500DT
designator C?  Capacitance: 3.9nF  (hidden comment: *)
Capacitor, Ceramic (MLCC), 3.9nF, ±10%, 50V, X7R, ±10%, SMD 1206; Manufacturer: CCTC; Manufacturer Part Number: TCC1206X7R392K500DT
footprint CAP-1206 (1206 (3216M) Capacitor)
pins: 1, 2

## TCC1206X7R393K500DT
designator C?  Capacitance: 39nF  (hidden comment: *)
Capacitor, Ceramic (MLCC), 39nF, ±10%, 50V, X7R, ±10%, SMD 1206; Manufacturer: CCTC; Manufacturer Part Number: TCC1206X7R393K500DT
footprint CAP-1206 (1206 (3216M) Capacitor)
pins: 1, 2

## TCC1206X7R471K102DTS
designator C?  Capacitance: 470pF  (hidden comment: *)
Capacitor, Ceramic (MLCC), 470pF, ±10%, 1kV, X7R, ±10%, SMD 1206; Manufacturer: CCTC; Manufacturer Part Number: TCC1206X7R471K102DTS
footprint CAP-1206 (1206 (3216M) Capacitor)
pins: 1, 2

## TCC1206X7R471K102FT
designator C?  Capacitance: 470pF  (hidden comment: *)
Capacitor, Ceramic (MLCC), 470pF, ±10%, 1kV, X7R, ±10%, SMD 1206; Manufacturer: CCTC; Manufacturer Part Number: TCC1206X7R471K102FT
footprint CAP-1206 (1206 (3216M) Capacitor)
pins: 1, 2

## TCC1206X7R471K202FT
designator C?  Capacitance: 470pF  (hidden comment: *)
Capacitor, Ceramic (MLCC), 470pF, ±10%, 2kV, X7R, ±10%, SMD 1206; Manufacturer: CCTC; Manufacturer Part Number: TCC1206X7R471K202FT
footprint CAP-1206 (1206 (3216M) Capacitor)
pins: 1, 2

## TCC1206X7R471K251DT
designator C?  Capacitance: 470pF  (hidden comment: *)
Capacitor, Ceramic (MLCC), 470pF, ±10%, 250V, X7R, ±10%, SMD 1206; Manufacturer: CCTC; Manufacturer Part Number: TCC1206X7R471K251DT
footprint CAP-1206 (1206 (3216M) Capacitor)
pins: 1, 2

## TCC1206X7R471K500DT
designator C?  Capacitance: 470pF  (hidden comment: *)
Capacitor, Ceramic (MLCC), 470pF, ±10%, 50V, X7R, ±10%, SMD 1206; Manufacturer: CCTC; Manufacturer Part Number: TCC1206X7R471K500DT
footprint CAP-1206 (1206 (3216M) Capacitor)
pins: 1, 2

## TCC1206X7R471K501DT
designator C?  Capacitance: 470pF  (hidden comment: *)
Capacitor, Ceramic (MLCC), 470pF, ±10%, 500V, X7R, ±10%, SMD 1206; Manufacturer: CCTC; Manufacturer Part Number: TCC1206X7R471K501DT
footprint CAP-1206 (1206 (3216M) Capacitor)
pins: 1, 2

## TCC1206X7R472K102DTS
designator C?  Capacitance: 4.7nF  (hidden comment: *)
Capacitor, Ceramic (MLCC), 4.7nF, ±10%, 1kV, X7R, ±10%, SMD 1206; Manufacturer: CCTC; Manufacturer Part Number: TCC1206X7R472K102DTS
footprint CAP-1206 (1206 (3216M) Capacitor)
pins: 1, 2

## TCC1206X7R472K102FT
designator C?  Capacitance: 4.7nF  (hidden comment: *)
Capacitor, Ceramic (MLCC), 4.7nF, ±10%, 1kV, X7R, ±10%, SMD 1206; Manufacturer: CCTC; Manufacturer Part Number: TCC1206X7R472K102FT
footprint CAP-1206 (1206 (3216M) Capacitor)
pins: 1, 2

## TCC1206X7R472K251DT
designator C?  Capacitance: 4.7nF  (hidden comment: *)
Capacitor, Ceramic (MLCC), 4.7nF, ±10%, 250V, X7R, ±10%, SMD 1206; Manufacturer: CCTC; Manufacturer Part Number: TCC1206X7R472K251DT
footprint CAP-1206 (1206 (3216M) Capacitor)
pins: 1, 2

## TCC1206X7R472K500DT
designator C?  Capacitance: 4.7nF  (hidden comment: *)
Capacitor, Ceramic (MLCC), 4.7nF, ±10%, 50V, X7R, ±10%, SMD 1206; Manufacturer: CCTC; Manufacturer Part Number: TCC1206X7R472K500DT
footprint CAP-1206 (1206 (3216M) Capacitor)
pins: 1, 2

## TCC1206X7R472K501DT
designator C?  Capacitance: 4.7nF  (hidden comment: *)
Capacitor, Ceramic (MLCC), 4.7nF, ±10%, 500V, X7R, ±10%, SMD 1206; Manufacturer: CCTC; Manufacturer Part Number: TCC1206X7R472K501DT
footprint CAP-1206 (1206 (3216M) Capacitor)
pins: 1, 2

## TCC1206X7R473K101DT
designator C?  Capacitance: 47nF  (hidden comment: *)
Capacitor, Ceramic (MLCC), 47nF, ±10%, 100V, X7R, ±10%, SMD 1206; Manufacturer: CCTC; Manufacturer Part Number: TCC1206X7R473K101DT
footprint CAP-1206 (1206 (3216M) Capacitor)
pins: 1, 2

## TCC1206X7R473K101FT
designator C?  Capacitance: 47nF  (hidden comment: *)
Capacitor, Ceramic (MLCC), 47nF, ±10%, 100V, X7R, ±10%, SMD 1206; Manufacturer: CCTC; Manufacturer Part Number: TCC1206X7R473K101FT
footprint CAP-1206 (1206 (3216M) Capacitor)
pins: 1, 2

## TCC1206X7R473K251FT
designator C?  Capacitance: 47nF  (hidden comment: *)
Capacitor, Ceramic (MLCC), 47nF, ±10%, 250V, X7R, ±10%, SMD 1206; Manufacturer: CCTC; Manufacturer Part Number: TCC1206X7R473K251FT
footprint CAP-1206 (1206 (3216M) Capacitor)
pins: 1, 2

## TCC1206X7R473K500DT
designator C?  Capacitance: 47nF  (hidden comment: *)
Capacitor, Ceramic (MLCC), 47nF, ±10%, 50V, X7R, ±10%, SMD 1206; Manufacturer: CCTC; Manufacturer Part Number: TCC1206X7R473K500DT
footprint CAP-1206 (1206 (3216M) Capacitor)
pins: 1, 2

## TCC1206X7R473K501FT
designator C?  Capacitance: 47nF  (hidden comment: *)
Capacitor, Ceramic (MLCC), 47nF, ±10%, 500V, X7R, ±10%, SMD 1206; Manufacturer: CCTC; Manufacturer Part Number: TCC1206X7R473K501FT
footprint CAP-1206 (1206 (3216M) Capacitor)
pins: 1, 2

## TCC1206X7R473K631HT
designator C?  Capacitance: 47nF  (hidden comment: *)
Capacitor, Ceramic (MLCC), 47nF, ±10%, 630V, X7R, ±10%, SMD 1206; Manufacturer: CCTC; Manufacturer Part Number: TCC1206X7R473K631HT
footprint CAP-1206 (1206 (3216M) Capacitor)
pins: 1, 2

## TCC1206X7R474K101FT
designator C?  Capacitance: 470nF  (hidden comment: *)
Capacitor, Ceramic (MLCC), 470nF, ±10%, 100V, X7R, ±10%, SMD 1206; Manufacturer: CCTC; Manufacturer Part Number: TCC1206X7R474K101FT
footprint CAP-1206 (1206 (3216M) Capacitor)
pins: 1, 2

## TCC1206X7R474K160FT
designator C?  Capacitance: 470nF  (hidden comment: *)
Capacitor, Ceramic (MLCC), 470nF, ±10%, 16V, X7R, ±10%, SMD 1206; Manufacturer: CCTC; Manufacturer Part Number: TCC1206X7R474K160FT
footprint CAP-1206 (1206 (3216M) Capacitor)
pins: 1, 2

## TCC1206X7R474K500FT
designator C?  Capacitance: 470nF  (hidden comment: *)
Capacitor, Ceramic (MLCC), 470nF, ±10%, 50V, X7R, ±10%, SMD 1206; Manufacturer: CCTC; Manufacturer Part Number: TCC1206X7R474K500FT
footprint CAP-1206 (1206 (3216M) Capacitor)
pins: 1, 2

## TCC1206X7R475K250HT
designator C?  Capacitance: 4.7uF  (hidden comment: *)
Capacitor, Ceramic (MLCC), 4.7uF, ±10%, 25V, X7R, ±10%, SMD 1206; Manufacturer: CCTC; Manufacturer Part Number: TCC1206X7R475K250HT
footprint CAP-1206 (1206 (3216M) Capacitor)
pins: 1, 2

## TCC1206X7R511K500DT
designator C?  Capacitance: 510pF  (hidden comment: *)
Capacitor, Ceramic (MLCC), 510pF, ±10%, 50V, X7R, ±10%, SMD 1206; Manufacturer: CCTC; Manufacturer Part Number: TCC1206X7R511K500DT
footprint CAP-1206 (1206 (3216M) Capacitor)
pins: 1, 2

## TCC1206X7R561K102FT
designator C?  Capacitance: 560pF  (hidden comment: *)
Capacitor, Ceramic (MLCC), 560pF, ±10%, 1kV, X7R, ±10%, SMD 1206; Manufacturer: CCTC; Manufacturer Part Number: TCC1206X7R561K102FT
footprint CAP-1206 (1206 (3216M) Capacitor)
pins: 1, 2

## TCC1206X7R561K500DTS
designator C?  Capacitance: 560pF  (hidden comment: *)
Capacitor, Ceramic (MLCC), 560pF, ±10%, 50V, X7R, ±10%, SMD 1206; Manufacturer: CCTC; Manufacturer Part Number: TCC1206X7R561K500DTS
footprint CAP-1206 (1206 (3216M) Capacitor)
pins: 1, 2

## TCC1206X7R561K501DT
designator C?  Capacitance: 560pF  (hidden comment: *)
Capacitor, Ceramic (MLCC), 560pF, ±10%, 500V, X7R, ±10%, SMD 1206; Manufacturer: CCTC; Manufacturer Part Number: TCC1206X7R561K501DT
footprint CAP-1206 (1206 (3216M) Capacitor)
pins: 1, 2

## TCC1206X7R562K102FT
designator C?  Capacitance: 5.6nF  (hidden comment: *)
Capacitor, Ceramic (MLCC), 5.6nF, ±10%, 1kV, X7R, ±10%, SMD 1206; Manufacturer: CCTC; Manufacturer Part Number: TCC1206X7R562K102FT
footprint CAP-1206 (1206 (3216M) Capacitor)
pins: 1, 2

## TCC1206X7R562K500DT
designator C?  Capacitance: 5.6nF  (hidden comment: *)
Capacitor, Ceramic (MLCC), 5.6nF, ±10%, 50V, X7R, ±10%, SMD 1206; Manufacturer: CCTC; Manufacturer Part Number: TCC1206X7R562K500DT
footprint CAP-1206 (1206 (3216M) Capacitor)
pins: 1, 2

## TCC1206X7R562K500DTS
designator C?  Capacitance: 5.6nF  (hidden comment: *)
Capacitor, Ceramic (MLCC), 5.6nF, ±10%, 50V, X7R, ±10%, SMD 1206; Manufacturer: CCTC; Manufacturer Part Number: TCC1206X7R562K500DTS
footprint CAP-1206 (1206 (3216M) Capacitor)
pins: 1, 2

## TCC1206X7R563K500DT
designator C?  Capacitance: 56nF  (hidden comment: *)
Capacitor, Ceramic (MLCC), 56nF, ±10%, 50V, X7R, ±10%, SMD 1206; Manufacturer: CCTC; Manufacturer Part Number: TCC1206X7R563K500DT
footprint CAP-1206 (1206 (3216M) Capacitor)
pins: 1, 2

## TCC1206X7R681K101DT
designator C?  Capacitance: 680pF  (hidden comment: *)
Capacitor, Ceramic (MLCC), 680pF, ±10%, 100V, X7R, ±10%, SMD 1206; Manufacturer: CCTC; Manufacturer Part Number: TCC1206X7R681K101DT
footprint CAP-1206 (1206 (3216M) Capacitor)
pins: 1, 2

## TCC1206X7R681K102DTS
designator C?  Capacitance: 680pF  (hidden comment: *)
Capacitor, Ceramic (MLCC), 680pF, ±10%, 1kV, X7R, ±10%, SMD 1206; Manufacturer: CCTC; Manufacturer Part Number: TCC1206X7R681K102DTS
footprint CAP-1206 (1206 (3216M) Capacitor)
pins: 1, 2

## TCC1206X7R681K102FT
designator C?  Capacitance: 680pF  (hidden comment: *)
Capacitor, Ceramic (MLCC), 680pF, ±10%, 1kV, X7R, ±10%, SMD 1206; Manufacturer: CCTC; Manufacturer Part Number: TCC1206X7R681K102FT
footprint CAP-1206 (1206 (3216M) Capacitor)
pins: 1, 2

## TCC1206X7R681K500DT
designator C?  Capacitance: 680pF  (hidden comment: *)
Capacitor, Ceramic (MLCC), 680pF, ±10%, 50V, X7R, ±10%, SMD 1206; Manufacturer: CCTC; Manufacturer Part Number: TCC1206X7R681K500DT
footprint CAP-1206 (1206 (3216M) Capacitor)
pins: 1, 2

## TCC1206X7R681K501DT
designator C?  Capacitance: 680pF  (hidden comment: *)
Capacitor, Ceramic (MLCC), 680pF, ±10%, 500V, X7R, ±10%, SMD 1206; Manufacturer: CCTC; Manufacturer Part Number: TCC1206X7R681K501DT
footprint CAP-1206 (1206 (3216M) Capacitor)
pins: 1, 2

## TCC1206X7R682K102FT
designator C?  Capacitance: 6.8nF  (hidden comment: *)
Capacitor, Ceramic (MLCC), 6.8nF, ±10%, 1kV, X7R, ±10%, SMD 1206; Manufacturer: CCTC; Manufacturer Part Number: TCC1206X7R682K102FT
footprint CAP-1206 (1206 (3216M) Capacitor)
pins: 1, 2

## TCC1206X7R683K500DT
designator C?  Capacitance: 68nF  (hidden comment: *)
Capacitor, Ceramic (MLCC), 68nF, ±10%, 50V, X7R, ±10%, SMD 1206; Manufacturer: CCTC; Manufacturer Part Number: TCC1206X7R683K500DT
footprint CAP-1206 (1206 (3216M) Capacitor)
pins: 1, 2

## TCC1206X7R684K500FT
designator C?  Capacitance: 680nF  (hidden comment: *)
Capacitor, Ceramic (MLCC), 680nF, ±10%, 50V, X7R, ±10%, SMD 1206; Manufacturer: CCTC; Manufacturer Part Number: TCC1206X7R684K500FT
footprint CAP-1206 (1206 (3216M) Capacitor)
pins: 1, 2

## TCC1206X7R822K500DT
designator C?  Capacitance: 8.2nF  (hidden comment: *)
Capacitor, Ceramic (MLCC), 8.2nF, ±10%, 50V, X7R, ±10%, SMD 1206; Manufacturer: CCTC; Manufacturer Part Number: TCC1206X7R822K500DT
footprint CAP-1206 (1206 (3216M) Capacitor)
pins: 1, 2

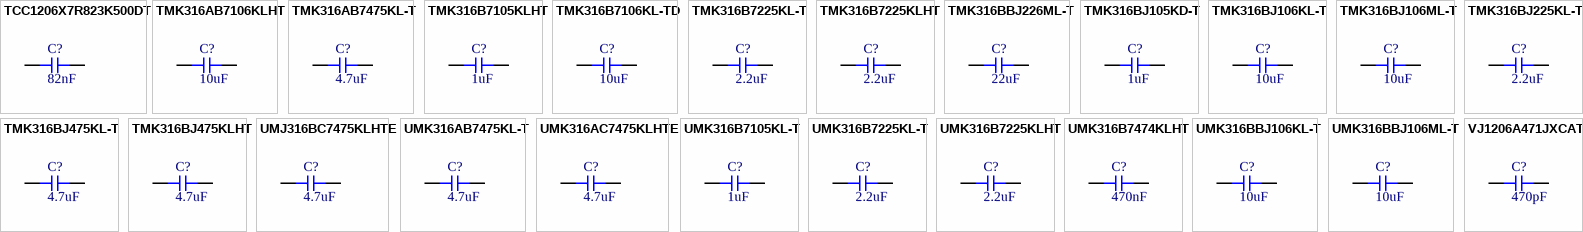
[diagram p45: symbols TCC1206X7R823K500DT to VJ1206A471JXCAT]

## TCC1206X7R823K500DT
designator C?  Capacitance: 82nF  (hidden comment: *)
Capacitor, Ceramic (MLCC), 82nF, ±10%, 50V, X7R, ±10%, SMD 1206; Manufacturer: CCTC; Manufacturer Part Number: TCC1206X7R823K500DT
footprint CAP-1206 (1206 (3216M) Capacitor)
pins: 1, 2

## TMK316AB7106KLHT
designator C?  Capacitance: 10uF  (hidden comment: *)
Capacitor, Ceramic (MLCC), 10uF, ±10%, 25V, X7R, ±10%, SMD 1206; Manufacturer: Taiyo Yuden; Manufacturer Part Number: TMK316AB7106KLHT
footprint CAP-1206 (1206 (3216M) Capacitor)
pins: 1, 2

## TMK316AB7475KL-T
designator C?  Capacitance: 4.7uF  (hidden comment: *)
Capacitor, Ceramic (MLCC), 4.7uF, ±10%, 25V, X7R, ±10%, SMD 1206; Manufacturer: Taiyo Yuden; Manufacturer Part Number: TMK316AB7475KL-T
footprint CAP-1206 (1206 (3216M) Capacitor)
pins: 1, 2

## TMK316B7105KLHT
designator C?  Capacitance: 1uF  (hidden comment: *)
Capacitor, Ceramic (MLCC), 1uF, ±10%, 25V, X7R, ±10%, SMD 1206; Manufacturer: Taiyo Yuden; Manufacturer Part Number: TMK316B7105KLHT
footprint CAP-1206 (1206 (3216M) Capacitor)
pins: 1, 2

## TMK316B7106KL-TD
designator C?  Capacitance: 10uF  (hidden comment: *)
Capacitor, Ceramic (MLCC), 10uF, ±10%, 25V, X7R, ±10%, SMD 1206; Manufacturer: Taiyo Yuden; Manufacturer Part Number: TMK316B7106KL-TD
footprint CAP-1206 (1206 (3216M) Capacitor)
pins: 1, 2

## TMK316B7225KL-T
designator C?  Capacitance: 2.2uF  (hidden comment: *)
Capacitor, Ceramic (MLCC), 2.2uF, ±10%, 25V, X7R, ±10%, SMD 1206; Manufacturer: Taiyo Yuden; Manufacturer Part Number: TMK316B7225KL-T
footprint CAP-1206 (1206 (3216M) Capacitor)
pins: 1, 2

## TMK316B7225KLHT
designator C?  Capacitance: 2.2uF  (hidden comment: *)
Capacitor, Ceramic (MLCC), 2.2uF, ±10%, 25V, X7R, ±10%, SMD 1206; Manufacturer: Taiyo Yuden; Manufacturer Part Number: TMK316B7225KLHT
footprint CAP-1206 (1206 (3216M) Capacitor)
pins: 1, 2

## TMK316BBJ226ML-T
designator C?  Capacitance: 22uF  (hidden comment: *)
Capacitor, Ceramic (MLCC), 22uF, ±20%, 25V, X5R, ±20%, SMD 1206; Manufacturer: Taiyo Yuden; Manufacturer Part Number: TMK316BBJ226ML-T
footprint CAP-1206 (1206 (3216M) Capacitor)
pins: 1, 2

## TMK316BJ105KD-T
designator C?  Capacitance: 1uF  (hidden comment: *)
Capacitor, Ceramic (MLCC), 1uF, ±10%, 25V, X5R, ±10%, SMD 1206; Manufacturer: Taiyo Yuden; Manufacturer Part Number: TMK316BJ105KD-T
footprint CAP-1206 (1206 (3216M) Capacitor)
pins: 1, 2

## TMK316BJ106KL-T
designator C?  Capacitance: 10uF  (hidden comment: *)
Capacitor, Ceramic (MLCC), 10uF, ±10%, 25V, X5R, ±10%, SMD 1206; Manufacturer: Taiyo Yuden; Manufacturer Part Number: TMK316BJ106KL-T
footprint CAP-1206 (1206 (3216M) Capacitor)
pins: 1, 2

## TMK316BJ106ML-T
designator C?  Capacitance: 10uF  (hidden comment: *)
Capacitor, Ceramic (MLCC), 10uF, ±20%, 25V, X5R, ±20%, SMD 1206; Manufacturer: Taiyo Yuden; Manufacturer Part Number: TMK316BJ106ML-T
footprint CAP-1206 (1206 (3216M) Capacitor)
pins: 1, 2

## TMK316BJ225KL-T
designator C?  Capacitance: 2.2uF  (hidden comment: *)
Capacitor, Ceramic (MLCC), 2.2uF, ±10%, 25V, X5R, ±10%, SMD 1206; Manufacturer: Taiyo Yuden; Manufacturer Part Number: TMK316BJ225KL-T
footprint CAP-1206 (1206 (3216M) Capacitor)
pins: 1, 2

## TMK316BJ475KL-T
designator C?  Capacitance: 4.7uF  (hidden comment: *)
Capacitor, Ceramic (MLCC), 4.7uF, ±10%, 25V, X5R, ±10%, SMD 1206; Manufacturer: Taiyo Yuden; Manufacturer Part Number: TMK316BJ475KL-T
footprint CAP-1206 (1206 (3216M) Capacitor)
pins: 1, 2

## TMK316BJ475KLHT
designator C?  Capacitance: 4.7uF  (hidden comment: *)
Capacitor, Ceramic (MLCC), 4.7uF, ±10%, 25V, X5R, ±10%, SMD 1206; Manufacturer: Taiyo Yuden; Manufacturer Part Number: TMK316BJ475KLHT
footprint CAP-1206 (1206 (3216M) Capacitor)
pins: 1, 2

## UMJ316BC7475KLHTE
designator C?  Capacitance: 4.7uF  (hidden comment: *)
Capacitor, Ceramic (MLCC), 4.7uF, ±10%, 50V, X7S, ±10%, SMD 1206; Manufacturer: Taiyo Yuden; Manufacturer Part Number: UMJ316BC7475KLHTE
footprint CAP-1206 (1206 (3216M) Capacitor)
pins: 1, 2

## UMK316AB7475KL-T
designator C?  Capacitance: 4.7uF  (hidden comment: *)
Capacitor, Ceramic (MLCC), 4.7uF, ±10%, 50V, X7R, ±10%, SMD 1206; Manufacturer: Taiyo Yuden; Manufacturer Part Number: UMK316AB7475KL-T
footprint CAP-1206 (1206 (3216M) Capacitor)
pins: 1, 2

## UMK316AC7475KLHTE
designator C?  Capacitance: 4.7uF  (hidden comment: *)
Capacitor, Ceramic (MLCC), 4.7uF, ±10%, 50V, ±10%, SMD 1206; Manufacturer: Taiyo Yuden; Manufacturer Part Number: UMK316AC7475KLHTE
footprint CAP-1206 (1206 (3216M) Capacitor)
pins: 1, 2

## UMK316B7105KL-T
designator C?  Capacitance: 1uF  (hidden comment: *)
Capacitor, Ceramic (MLCC), 1uF, ±10%, 50V, X7R, ±10%, SMD 1206; Manufacturer: Taiyo Yuden; Manufacturer Part Number: UMK316B7105KL-T
footprint CAP-1206 (1206 (3216M) Capacitor)
pins: 1, 2

## UMK316B7225KL-T
designator C?  Capacitance: 2.2uF  (hidden comment: *)
Capacitor, Ceramic (MLCC), 2.2uF, ±10%, 50V, X7R, ±10%, SMD 1206; Manufacturer: Taiyo Yuden; Manufacturer Part Number: UMK316B7225KL-T
footprint CAP-1206 (1206 (3216M) Capacitor)
pins: 1, 2

## UMK316B7225KLHT
designator C?  Capacitance: 2.2uF  (hidden comment: *)
Capacitor, Ceramic (MLCC), 2.2uF, ±10%, 50V, X7R, ±10%, SMD 1206; Manufacturer: Taiyo Yuden; Manufacturer Part Number: UMK316B7225KLHT
footprint CAP-1206 (1206 (3216M) Capacitor)
pins: 1, 2

## UMK316B7474KLHT
designator C?  Capacitance: 470nF  (hidden comment: *)
Capacitor, Ceramic (MLCC), 470nF, ±10%, 50V, X7R, ±10%, SMD 1206; Manufacturer: Taiyo Yuden; Manufacturer Part Number: UMK316B7474KLHT
footprint CAP-1206 (1206 (3216M) Capacitor)
pins: 1, 2

## UMK316BBJ106KL-T
designator C?  Capacitance: 10uF  (hidden comment: *)
Capacitor, Ceramic (MLCC), 10uF, ±10%, 50V, X5R, ±10%, SMD 1206; Manufacturer: Taiyo Yuden; Manufacturer Part Number: UMK316BBJ106KL-T
footprint CAP-1206 (1206 (3216M) Capacitor)
pins: 1, 2

## UMK316BBJ106ML-T
designator C?  Capacitance: 10uF  (hidden comment: *)
Capacitor, Ceramic (MLCC), 10uF, ±20%, 50V, X5R, ±20%, SMD 1206; Manufacturer: Taiyo Yuden; Manufacturer Part Number: UMK316BBJ106ML-T
footprint CAP-1206 (1206 (3216M) Capacitor)
pins: 1, 2

## VJ1206A471JXCAT
designator C?  Capacitance: 470pF  (hidden comment: *)
Capacitor, Ceramic (MLCC), 470pF, ±5%, 200V, C0G, ±5%, SMD 1206; Manufacturer: Vishay Intertech; Manufacturer Part Number: VJ1206A471JXCAT
footprint CAP-1206 (1206 (3216M) Capacitor)
pins: 1, 2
